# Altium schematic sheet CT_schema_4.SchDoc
size 218 x 153 mm
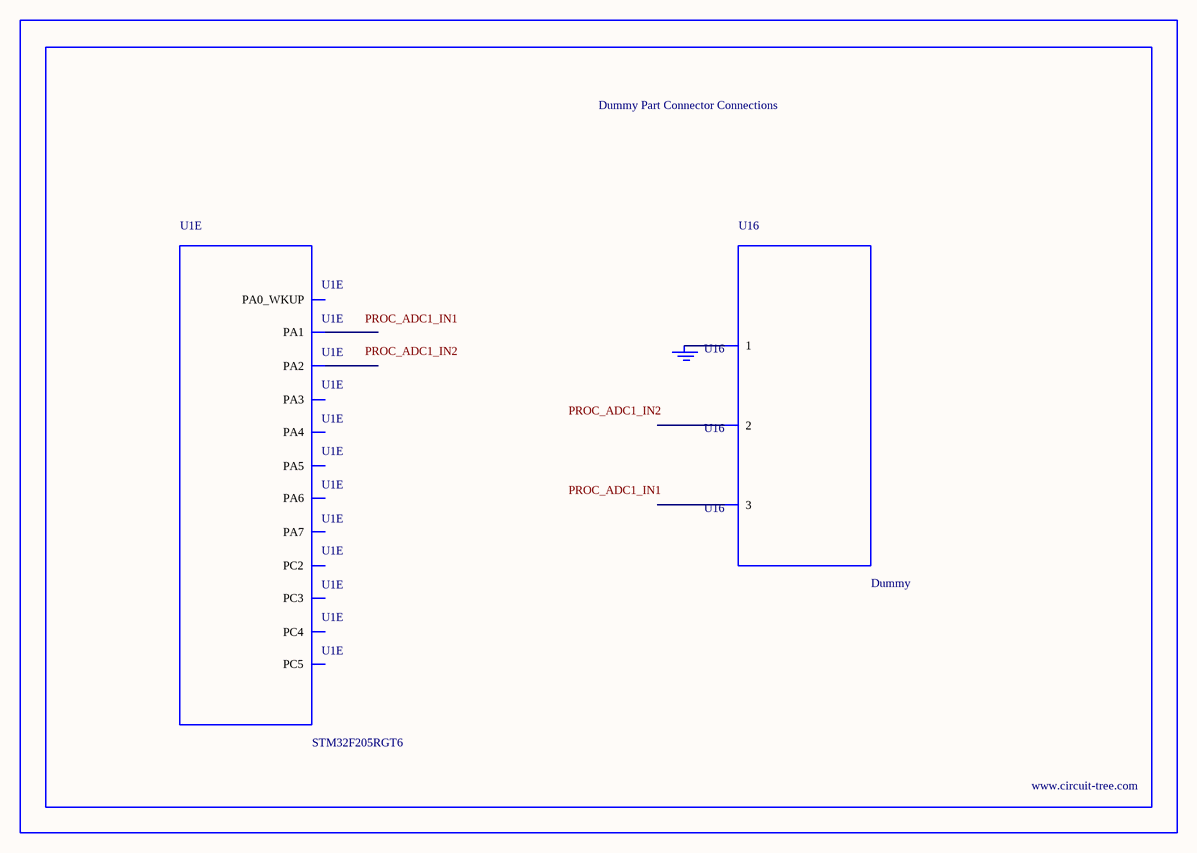
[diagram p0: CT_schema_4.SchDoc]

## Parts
BORDER3  (no value)
GND_INSTANCE_3_0  (no value)
U1  STM32F205RGT6  [LQFP64]  (part E of 5)
U16  Dummy  [DUMMY_PACKAGE_133]

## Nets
NetGND_INSTANCE_3_0_0: GND_INSTANCE_3_0.0(GND) U16.1

Not connected (* = marked no-connect by the designer): U1 10(PC2) 11(PC3) 14(PA0_WKUP) 15(PA1) 16(PA2) 17(PA3) 20(PA4) 21(PA5) 22(PA6) 23(PA7) 24(PC4) 25(PC5); U16 2 3

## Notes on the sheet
- Labels drawn without touching a wire or pin: PROC_ADC1_IN1, PROC_ADC1_IN2

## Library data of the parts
BORDER3 = BORDER_PAGE3
GND_INSTANCE_3_0 = GND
